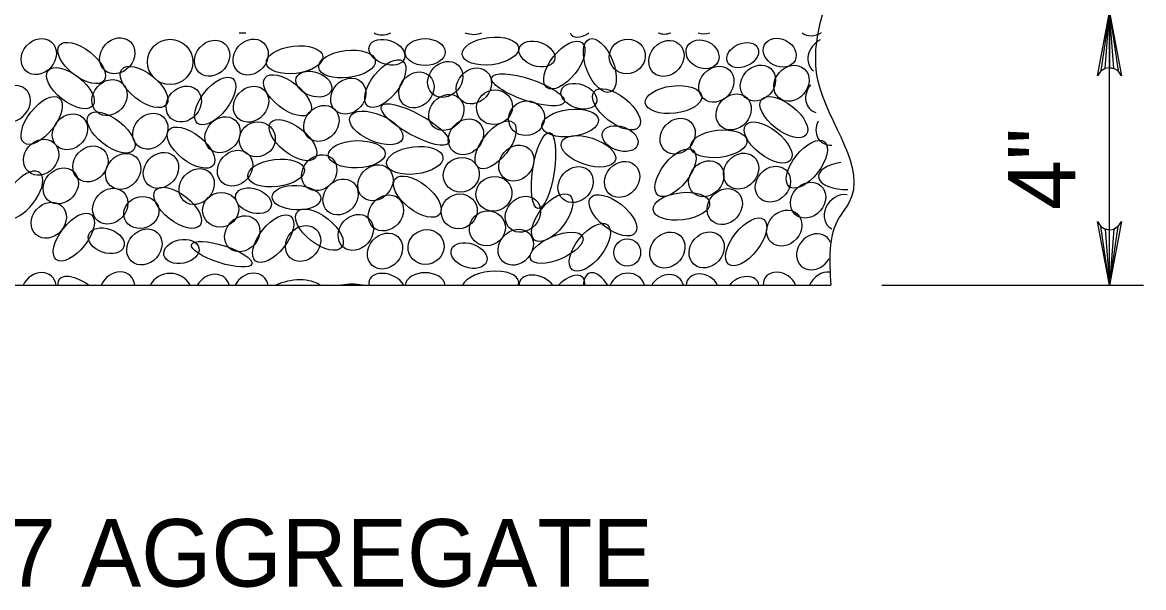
# Model space of a CAD drawing. Extents: x 1.32 to 7.47, y -3.56 to 5.14.
# Drawn here: x 3.855 to 4.852, y -1.203 to -0.701 of the extents above; entities that cross this region are included whole.
import ezdxf

# ---------------------------------------------------------------- set-up
doc = ezdxf.new("R2010")
doc.units = 0
for name, color, linetype in [('DETL-DIMS', 7, 'Continuous'), ('DETL-LINE', 7, 'Continuous'), ('DETL-NOTE', 7, 'Continuous'), ('DETL-PATT', 7, 'Continuous')]:
    doc.layers.add(name, color=color, linetype=linetype)

msp = doc.modelspace()

# ---------------------------------------------------------------- linework, layer by layer
at = {"layer": 'DETL-DIMS'}
for p, q in [((4.82214, -0.93409), (4.82214, -0.69166)), ((4.61982, -0.93409), (4.85245, -0.93409))]:
    msp.add_line(p, q, dxfattribs=at)
for points in [[(4.82214, -0.69166), (4.83273, -0.74815), (4.82972, -0.7438), (4.82593, -0.74155), (4.82214, -0.74091), (4.81836, -0.74155), (4.81457, -0.7438), (4.81155, -0.74815), (4.82214, -0.69166), (4.81457, -0.7438), (4.81836, -0.74155), (4.82214, -0.69166), (4.82214, -0.74091), (4.82593, -0.74155), (4.82214, -0.69166), (4.82972, -0.7438)], [(4.82214, -0.93409), (4.81155, -0.8776), (4.81457, -0.88195), (4.81836, -0.8842), (4.82214, -0.88484), (4.82593, -0.8842), (4.82972, -0.88195), (4.83273, -0.8776), (4.82214, -0.93409), (4.82972, -0.88195), (4.82593, -0.8842), (4.82214, -0.93409), (4.82214, -0.88484), (4.81836, -0.8842), (4.82214, -0.93409), (4.81457, -0.88195)]]:
    msp.add_lwpolyline(points, dxfattribs=at)
at = {"layer": 'DETL-LINE'}
msp.add_line((3.11982, -0.93409), (4.57437, -0.93409), dxfattribs=at)
msp.add_spline([(4.60467, 0.88409), (4.59785, 0.85492), (4.58218, 0.82357), (4.55477, 0.73735), (4.59393, 0.65506), (4.59785, 0.59236), (4.59785, 0.50223), (4.59002, 0.41993), (4.57435, 0.32196), (4.59002, 0.23575), (4.6096, 0.14562), (4.59002, 0.07116), (4.54302, -0.01897), (4.56652, -0.16789), (4.57827, -0.24626), (4.55085, -0.32072), (4.5626, -0.40693), (4.60568, -0.51666), (4.59785, -0.59895), (4.57043, -0.68125), (4.5626, -0.75179), (4.59002, -0.86151), (4.58218, -0.87327), (4.57437, -0.93409)], degree=3, dxfattribs=at)
at = {"layer": 'DETL-PATT'}
msp.add_circle((3.98683, -0.73576), 0.02014, dxfattribs=at)
msp.add_arc((3.98683, -0.94373), 0.02014, 28.61854, 151.38146, dxfattribs=at)
for centre, major_axis, ratio in [((3.86998, -0.73097), (0.01137, 0.01279), 0.844245), ((3.90813, -0.73671), (-0.0199, 0.01564), 0.479042), ((3.93979, -0.73031), (0.01137, 0.01279), 0.844245), ((4.02411, -0.73246), (0.01137, 0.01279), 0.844245), ((4.05842, -0.73144), (0.01137, 0.01279), 0.844245), ((4.17958, -0.72718), (0.01559, -0.0055), 0.646802), ((4.21353, -0.72703), (0.0178, 0), 0.671766), ((4.27161, -0.72616), (-0.02513, -0.00302), 0.479042), ((4.31302, -0.7287), (0.01559, -0.0055), 0.646802), ((4.33736, -0.73853), (-0.01564, -0.0199), 0.479042), ((4.36893, -0.73897), (0.00942, -0.02349), 0.479042), ((4.39331, -0.73086), (0.01499, 0.00599), 0.948581), ((4.42813, -0.73266), (0.01137, 0.01279), 0.844245), ((4.46023, -0.72899), (0.01358, -0.00697), 0.796199), ((4.49596, -0.72967), (-0.01361, -0.00614), 0.687276), ((4.5289, -0.72755), (0.01358, -0.00697), 0.796199), ((4.09755, -0.73386), (-0.02513, -0.00302), 0.479042), ((4.14409, -0.73762), (-0.02513, -0.00302), 0.479042), ((3.96362, -0.75802), (-0.0199, 0.01564), 0.479042), ((4.17815, -0.75504), (-0.01564, -0.0199), 0.479042), ((4.23148, -0.75128), (0.01137, 0.01279), 0.844245), ((4.47255, -0.7556), (0.01137, 0.01279), 0.844245), ((4.50952, -0.7545), (0.01137, 0.01279), 0.844245), ((4.53936, -0.75474), (0.01137, 0.01279), 0.844245), ((3.89813, -0.75908), (-0.0199, 0.01564), 0.479042), ((4.02686, -0.77046), (-0.01564, -0.0199), 0.479042), ((4.09113, -0.76539), (-0.0199, 0.01564), 0.479042), ((4.11461, -0.75548), (0.01559, -0.0055), 0.646802), ((4.20584, -0.76066), (0.01137, 0.01279), 0.844245), ((4.25692, -0.75706), (0.01137, 0.01279), 0.844245), ((4.30508, -0.76056), (0.03231, -0.01093), 0.282192), ((3.93294, -0.76739), (0.01137, 0.01279), 0.844245), ((3.99894, -0.77314), (0.01137, 0.01279), 0.844245), ((4.05877, -0.7733), (0.01137, 0.01279), 0.844245), ((4.14525, -0.76613), (0.01137, 0.01279), 0.844245), ((4.35028, -0.76623), (0.01559, -0.0055), 0.646802), ((4.38371, -0.77782), (-0.0199, 0.01564), 0.479042), ((4.43451, -0.76919), (-0.02513, -0.00302), 0.479042), ((3.87261, -0.78776), (-0.01564, -0.0199), 0.479042), ((4.23242, -0.78065), (0.01137, 0.01279), 0.844245), ((4.27528, -0.77603), (0.01499, 0.00599), 0.948581), ((4.48797, -0.78018), (0.01137, 0.01279), 0.844245), ((4.53258, -0.78483), (-0.0199, 0.01564), 0.479042), ((3.93438, -0.79848), (-0.0199, 0.01564), 0.479042), ((4.12132, -0.79035), (0.01137, 0.01279), 0.844245), ((4.20463, -0.79143), (0.02992, -0.01638), 0.282192), ((4.30376, -0.78582), (0.01499, 0.00599), 0.948581), ((4.34262, -0.79001), (-0.02513, -0.00302), 0.479042), ((3.89773, -0.79787), (0.01137, 0.01279), 0.844245), ((3.96919, -0.79729), (0.01137, 0.01279), 0.844245), ((4.03342, -0.80041), (0.01137, 0.01279), 0.844245), ((4.06432, -0.80451), (0.01499, 0.00599), 0.948581), ((4.09605, -0.80529), (-0.0199, 0.01564), 0.479042), ((4.17007, -0.79441), (-0.02327, 0.00995), 0.479042), ((4.24987, -0.8023), (0.01137, 0.01279), 0.844245), ((4.27625, -0.80939), (-0.01564, -0.0199), 0.479042), ((4.43815, -0.80172), (0.01137, 0.01279), 0.844245), ((4.51857, -0.80741), (-0.0199, 0.01564), 0.479042), ((4.00535, -0.8119), (-0.0199, 0.01564), 0.479042), ((4.38696, -0.80386), (0.01559, -0.0055), 0.646802), ((4.47462, -0.80852), (-0.02513, -0.00302), 0.479042), ((3.87211, -0.82041), (0.01137, 0.01279), 0.844245), ((4.15274, -0.81781), (-0.0253, -0.00081), 0.479042), ((4.31887, -0.83222), (0.00515, 0.03372), 0.282192), ((4.35874, -0.81516), (-0.02405, 0.00789), 0.479042), ((4.55303, -0.82669), (-0.01564, -0.0199), 0.479042), ((3.91597, -0.8264), (0.01137, 0.01279), 0.844245), ((3.94504, -0.833), (0.01137, 0.01279), 0.844245), ((3.97865, -0.83211), (0.01137, 0.01279), 0.844245), ((4.04455, -0.83016), (0.01137, 0.01279), 0.844245), ((4.11939, -0.83416), (0.01137, 0.01279), 0.844245), ((4.2043, -0.82327), (-0.02513, -0.00302), 0.479042), ((4.2947, -0.82569), (0.01137, 0.01279), 0.844245), ((4.43624, -0.8342), (-0.01564, -0.0199), 0.479042), ((4.49453, -0.83279), (0.01137, 0.01279), 0.844245), ((4.08107, -0.83446), (-0.02513, -0.00302), 0.479042), ((4.16941, -0.84314), (0.01137, 0.01279), 0.844245), ((4.24571, -0.83602), (0.01499, 0.00599), 0.948581), ((4.34738, -0.84473), (0.01137, 0.01279), 0.844245), ((4.3887, -0.84017), (0.01137, 0.01279), 0.844245), ((4.46358, -0.83951), (0.01137, 0.01279), 0.844245), ((4.52283, -0.84437), (0.01137, 0.01279), 0.844245), ((3.88958, -0.84593), (0.01137, 0.01279), 0.844245), ((4.01043, -0.84649), (0.01137, 0.01279), 0.844245), ((4.20665, -0.85547), (-0.0199, 0.01564), 0.479042), ((4.27476, -0.8529), (0.01499, 0.00599), 0.948581), ((3.93357, -0.86391), (0.01137, 0.01279), 0.844245), ((3.99349, -0.86534), (-0.0199, 0.01564), 0.479042), ((4.06091, -0.85913), (0.01559, -0.0055), 0.646802), ((4.09914, -0.85639), (0.02166, -0.00089), 0.504072), ((4.13838, -0.85575), (0.01137, 0.01279), 0.844245), ((4.48002, -0.86428), (0.01137, 0.01279), 0.844245), ((4.5541, -0.85859), (0.01137, 0.01279), 0.844245), ((3.96123, -0.86954), (-0.01483, -0.00593), 0.87402), ((4.03176, -0.86712), (0.01499, 0.00599), 0.948581), ((4.17871, -0.86993), (0.01137, 0.01279), 0.844245), ((4.24388, -0.86851), (0.01499, 0.00599), 0.948581), ((4.30048, -0.87108), (0.01137, 0.01279), 0.844245), ((4.32655, -0.87414), (-0.01564, -0.0199), 0.479042), ((4.38058, -0.87211), (-0.0199, 0.01564), 0.479042), ((4.44145, -0.86402), (-0.02513, -0.00302), 0.479042), ((3.87888, -0.8764), (0.01137, 0.01279), 0.844245), ((4.11957, -0.88477), (-0.0199, 0.01564), 0.479042), ((4.26893, -0.88358), (0.01499, 0.00599), 0.948581), ((4.53293, -0.88343), (0.01137, 0.01279), 0.844245), ((3.90112, -0.89141), (-0.01564, -0.0199), 0.479042), ((4.05092, -0.88841), (0.01137, 0.01279), 0.844245), ((4.07843, -0.89279), (-0.01564, -0.0199), 0.479042), ((4.15187, -0.88723), (0.01137, 0.01279), 0.844245), ((4.36008, -0.90045), (-0.01564, -0.0199), 0.479042), ((4.49905, -0.89564), (-0.01564, -0.0199), 0.479042), ((3.93005, -0.89466), (0.01559, -0.0055), 0.646802), ((3.96391, -0.9001), (0.01137, 0.01279), 0.844245), ((4.10507, -0.89708), (0.01137, 0.01279), 0.844245), ((4.1779, -0.90378), (0.01137, 0.01279), 0.844245), ((4.21441, -0.9002), (0.01499, 0.00599), 0.948581), ((4.29413, -0.90036), (0.01137, 0.01279), 0.844245), ((4.33042, -0.90085), (-0.02318, -0.00983), 0.422273), ((4.42898, -0.90291), (0.01137, 0.01279), 0.844245), ((4.46392, -0.90276), (0.01137, 0.01279), 0.844245), ((3.99689, -0.90419), (-0.01559, -0.00312), 0.666084), ((4.03268, -0.9066), (-0.02684, 0.00859), 0.276285), ((4.25261, -0.90778), (0.01559, -0.0055), 0.646802), ((4.39333, -0.9051), (0, 0.01208), 0.982495)]:
    msp.add_ellipse(centre, major_axis=major_axis, ratio=ratio, dxfattribs=at)
for centre, major_axis, ratio, start_param, end_param in [((4.03268, -0.69864), (-0.02684, 0.00859), 0.276285, 2.272763, 2.585956), ((4.1779, -0.69582), (0.01137, 0.01279), 0.844245, 3.284375, 4.286464), ((4.25261, -0.69981), (0.01559, -0.0055), 0.646802, 4.702386, 5.72138), ((4.36008, -0.69248), (-0.01564, -0.0199), 0.479042, 6.027581, 7.258744), ((4.42898, -0.69495), (0.01137, 0.01279), 0.844245, 3.412723, 4.158116), ((4.46392, -0.69479), (0.01137, 0.01279), 0.844245, 3.440776, 4.130063), ((4.55953, -0.6965), (0.01137, 0.01279), 0.844245, 3.201447, 4.388677), ((4.56963, -0.73039), (0.01137, 0.01279), 0.844245, 1.128809, 3.203157), ((3.84689, -0.77281), (0.01137, 0.01279), 0.844245, 3.966094, 7.08108), ((4.56757, -0.76518), (0.01137, 0.01279), 0.844245, 1.607925, 3.526375), ((4.57677, -0.79369), (0.01137, 0.01279), 0.844245, 1.878687, 3.84974), ((4.58865, -0.83689), (-0.0253, -0.00081), 0.479042, 4.909641, 7.873235), ((3.85532, -0.85407), (-0.01564, -0.0199), 0.479042, 0.557656, 4.630471), ((4.58405, -0.86958), (0.01137, 0.01279), 0.844245, 0.507783, 3.351462), ((4.55953, -0.90447), (0.01137, 0.01279), 0.844245, 5.904883, 11.244012), ((3.86998, -0.93894), (0.01137, 0.01279), 0.844245, 5.664418, 8.189607), ((3.90813, -0.94468), (-0.0199, 0.01564), 0.479042, 4.781558, 6.689755), ((3.93979, -0.93828), (0.01137, 0.01279), 0.844245, 5.62113, 8.232895), ((4.02411, -0.94043), (0.01137, 0.01279), 0.844245, 5.764141, 8.089883), ((4.05842, -0.9394), (0.01137, 0.01279), 0.844245, 5.695119, 8.158905), ((4.17958, -0.93514), (0.01559, -0.0055), 0.646802, 0.591657, 3.548924), ((4.21353, -0.935), (0.0178, 0), 0.671766, 0.076424, 3.065169), ((4.27161, -0.93413), (-0.02513, -0.00302), 0.479042, 2.899214, 6.034599), ((4.31302, -0.93667), (0.01559, -0.0055), 0.646802, 0.725844, 3.414737), ((4.33736, -0.94649), (-0.01564, -0.0199), 0.479042, 2.553733, 4.449407), ((4.36893, -0.94694), (0.00942, -0.02349), 0.479042, 1.948382, 3.955368), ((4.39331, -0.93883), (0.01499, 0.00599), 0.948581, 6.196758, 8.713186), ((4.42813, -0.94063), (0.01137, 0.01279), 0.844245, 5.777379, 8.076646), ((4.46023, -0.93695), (0.01358, -0.00697), 0.796199, 0.797555, 3.489711), ((4.49596, -0.93764), (-0.01361, -0.00614), 0.687276, 2.883842, 5.379541), ((4.5289, -0.93552), (0.01358, -0.00697), 0.796199, 0.684096, 3.603171), ((4.56963, -0.93836), (0.01137, 0.01279), 0.844245, 0.556365, 1.944103), ((4.09755, -0.94183), (-0.02513, -0.00302), 0.479042, 3.569496, 5.364317), ((4.14409, -0.94558), (-0.02513, -0.00302), 0.479042, 4.081115, 4.852698)]:
    msp.add_ellipse(centre, major_axis=major_axis, ratio=ratio, start_param=start_param, end_param=end_param, dxfattribs=at)

# ---------------------------------------------------------------- texts
at = {"layer": 'DETL-NOTE'}
msp.add_text('4"', height=0.06, rotation=90, dxfattribs=at).set_placement((4.79184, -0.86748))
msp.add_text('NO. 57 AGGREGATE', height=0.06, dxfattribs=at).set_placement((3.63113, -1.20193))

doc.saveas('drawing.dxf')
